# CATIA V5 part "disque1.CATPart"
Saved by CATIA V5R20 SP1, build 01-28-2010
Part number: disque1
Bounding box of the stored display mesh (mm): x 42.5 to 117.5, y 0 to 15, z 62.5 to 137.5
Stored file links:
  E:\EDELI\gcausse\Edeli_2012_184_gcausse\disque1.CATPart
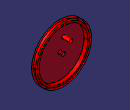
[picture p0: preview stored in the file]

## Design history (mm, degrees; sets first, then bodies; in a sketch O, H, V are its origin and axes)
Body1 (main body)
  DatumSurface1
  Sketch1 on face of DatumSurface1, origin (0, 5, 0), H (1, 0, 0), V (0, 0, 1)
    circle A1 centre (80, 100) radius 32.5
    circle A2 centre (80, 100) radius 2.5
    radius A1 = 32.5
    radius A2 = 2.5
  Pad1: profile Sketch1, direction (0, -1, 0), length 5
Body2
  Sketch2 on start face of Pad1, origin (0, 5, 0), H (-1, 0, 0), V (0, 0, 1)
    circle A1 centre (-80, 100) radius 35
    circle A2 centre (-80, 100) radius 32.5
    radius A2 = 32.5
    radius A1 = 35
  Pad2: profile Sketch2, direction (0, -1, 0), length 5
  Sketch3 on start face of Pad1, origin (0, 5, 0), H (-1, 0, 0), V (0, 0, 1)
Body3
  Sketch4 on start face of Pad1, origin (0, 5, 0), H (-1, 0, 0), V (0, 0, 1)
    circle A1 centre (-80, 100) radius 37.5
    circle A2 centre (-80, 100) radius 35
    radius A2 = 35
    radius A1 = 37.5
  Pad3: profile Sketch4, direction (0, -1, 0), length 5
  Sketch5 on start face of Pad1, origin (0, 5, 0), H (-1, 0, 0), V (0, 0, 1)
    circle A1 centre (-80, 120) radius 2.5
    radius A1 = 2.5
  Pad4: profile Sketch5, direction (0, 1, 0), length 10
